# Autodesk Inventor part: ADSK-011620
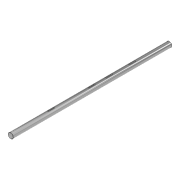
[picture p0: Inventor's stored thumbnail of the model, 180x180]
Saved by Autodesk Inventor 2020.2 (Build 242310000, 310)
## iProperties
Created: 2000-02
Part Number: ADSK-011620
Material: Pearson CD 1018
Document SubType Name: Modeling
Designer: sspink
Density: 7.83 g/cm^3
Appearance: Chrom - poliert
Mass: 2849.08 g
Surface Area: 600.119 cm^2
Volume: 363.867 cm^3
Control State: 0
Checked Out: False
Master: False
Shininess: 60.0
Length Units: 11269
Angle Units: 11279
Time Units: 11290
Mass Units: 11283
Length Display Precision: 3
Angle Display Precision: 2
Compacted: True
Cutlength: 23.25
Material Desc: Material Description goes here
Material_Number: Pearson
Dimensions: 25x745x25 mm
Mass: 2,849 kg
DocNumber: ADSK-011620.ipt
Folder: 01 - Themengebiete\Simplification\01 - Packaging machine\
VDS_Category: 3D Komponenten
VLT_Material: Pearson CD 1018
Density: 7.830000000000001
Volumn: 386.1110990722932
Area: 618.1831244989472
PropertySet Name: Model Information
Author: sspink
Revision Number: -
Title: shaft
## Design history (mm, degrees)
node "Rectangular Pattern1" dims "d9" = 30, "d11" = 190
node "Rectangular Pattern2" dims "d12" = 20, "d14" = 272
node "Solide1"
  node "Extrusion1" dims "d1" = 745, "d2" = 0
  node "Extrusion2" dims "d7" = 32, "d8" = 0
  node "Chamfer1" dims "d15" = 1, "d16" = 45 deg, "d20" = 0.762
  node "Chamfer2" dims "d17" = 1, "d18" = 45 deg, "d21" = 0.762
sketch "Sketch1"
  geometry: C1 r 12.5 at (0, 0); 1 further point
  constraints: 1 centre point, 1 coincident
  dimensions: "d0" = 25 diameter of C1
workplane "Work Plane1"
sketch "Sketch2"
  geometry: L1 (-3, 12.135)-(-3, 10); L2 (-3, 10)-(3, 10); L3 (3, 12.135)-(3, 10); A1 r 12.5 centre (0, 0) between (-3, 12.135) and (3, 12.135) reference
  constraints: 6 end point, 2 perpendicular, 2 point on circle, 1 vertical
  dimensions: "d5" = 6 distance between parallel lines of L3 L1; "d6" = 3 distance from line of A1.centre L1 (= 0.5 x d5); "d19" = 10 distance from line of A1.centre L2
fillet "Rundung1"
fillet "Rundung2"
node "Corps solides"
node "Corps surfaciques"
other parameters: "d3" = -174
